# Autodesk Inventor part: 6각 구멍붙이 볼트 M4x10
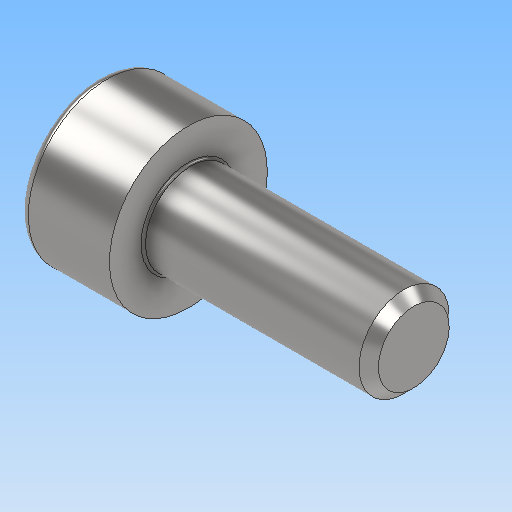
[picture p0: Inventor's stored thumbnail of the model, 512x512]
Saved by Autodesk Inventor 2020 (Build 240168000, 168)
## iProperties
Created: 2025-11
Part Number: 6각 구멍붙이 볼트 M4x10
Material: 강철, 연강
Description: 6각머리 태핑 나사
Document SubType Name: Modeling
Designer: PC2-06
Density: 7.85 g/cm^3
Appearance: 기본값
Author: jhkim
Sending System: Autodesk Inventor 2026
Preprocessor: ST-DEVELOPER v20.1
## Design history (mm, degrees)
feature "Solid1"
node "솔리드1"
